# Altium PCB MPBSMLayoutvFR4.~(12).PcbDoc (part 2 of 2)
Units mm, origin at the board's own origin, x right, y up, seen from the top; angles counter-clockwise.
Board outline 131.7 x 110.39 mm, 4 copper layers (Top Layer, Power, GroundPlane, Bottom Layer), stack 2.286 mm thick; 156 components, 77 nets, 429 pads, 117 vias.
Unrouted connection lines stored in the file: 25.
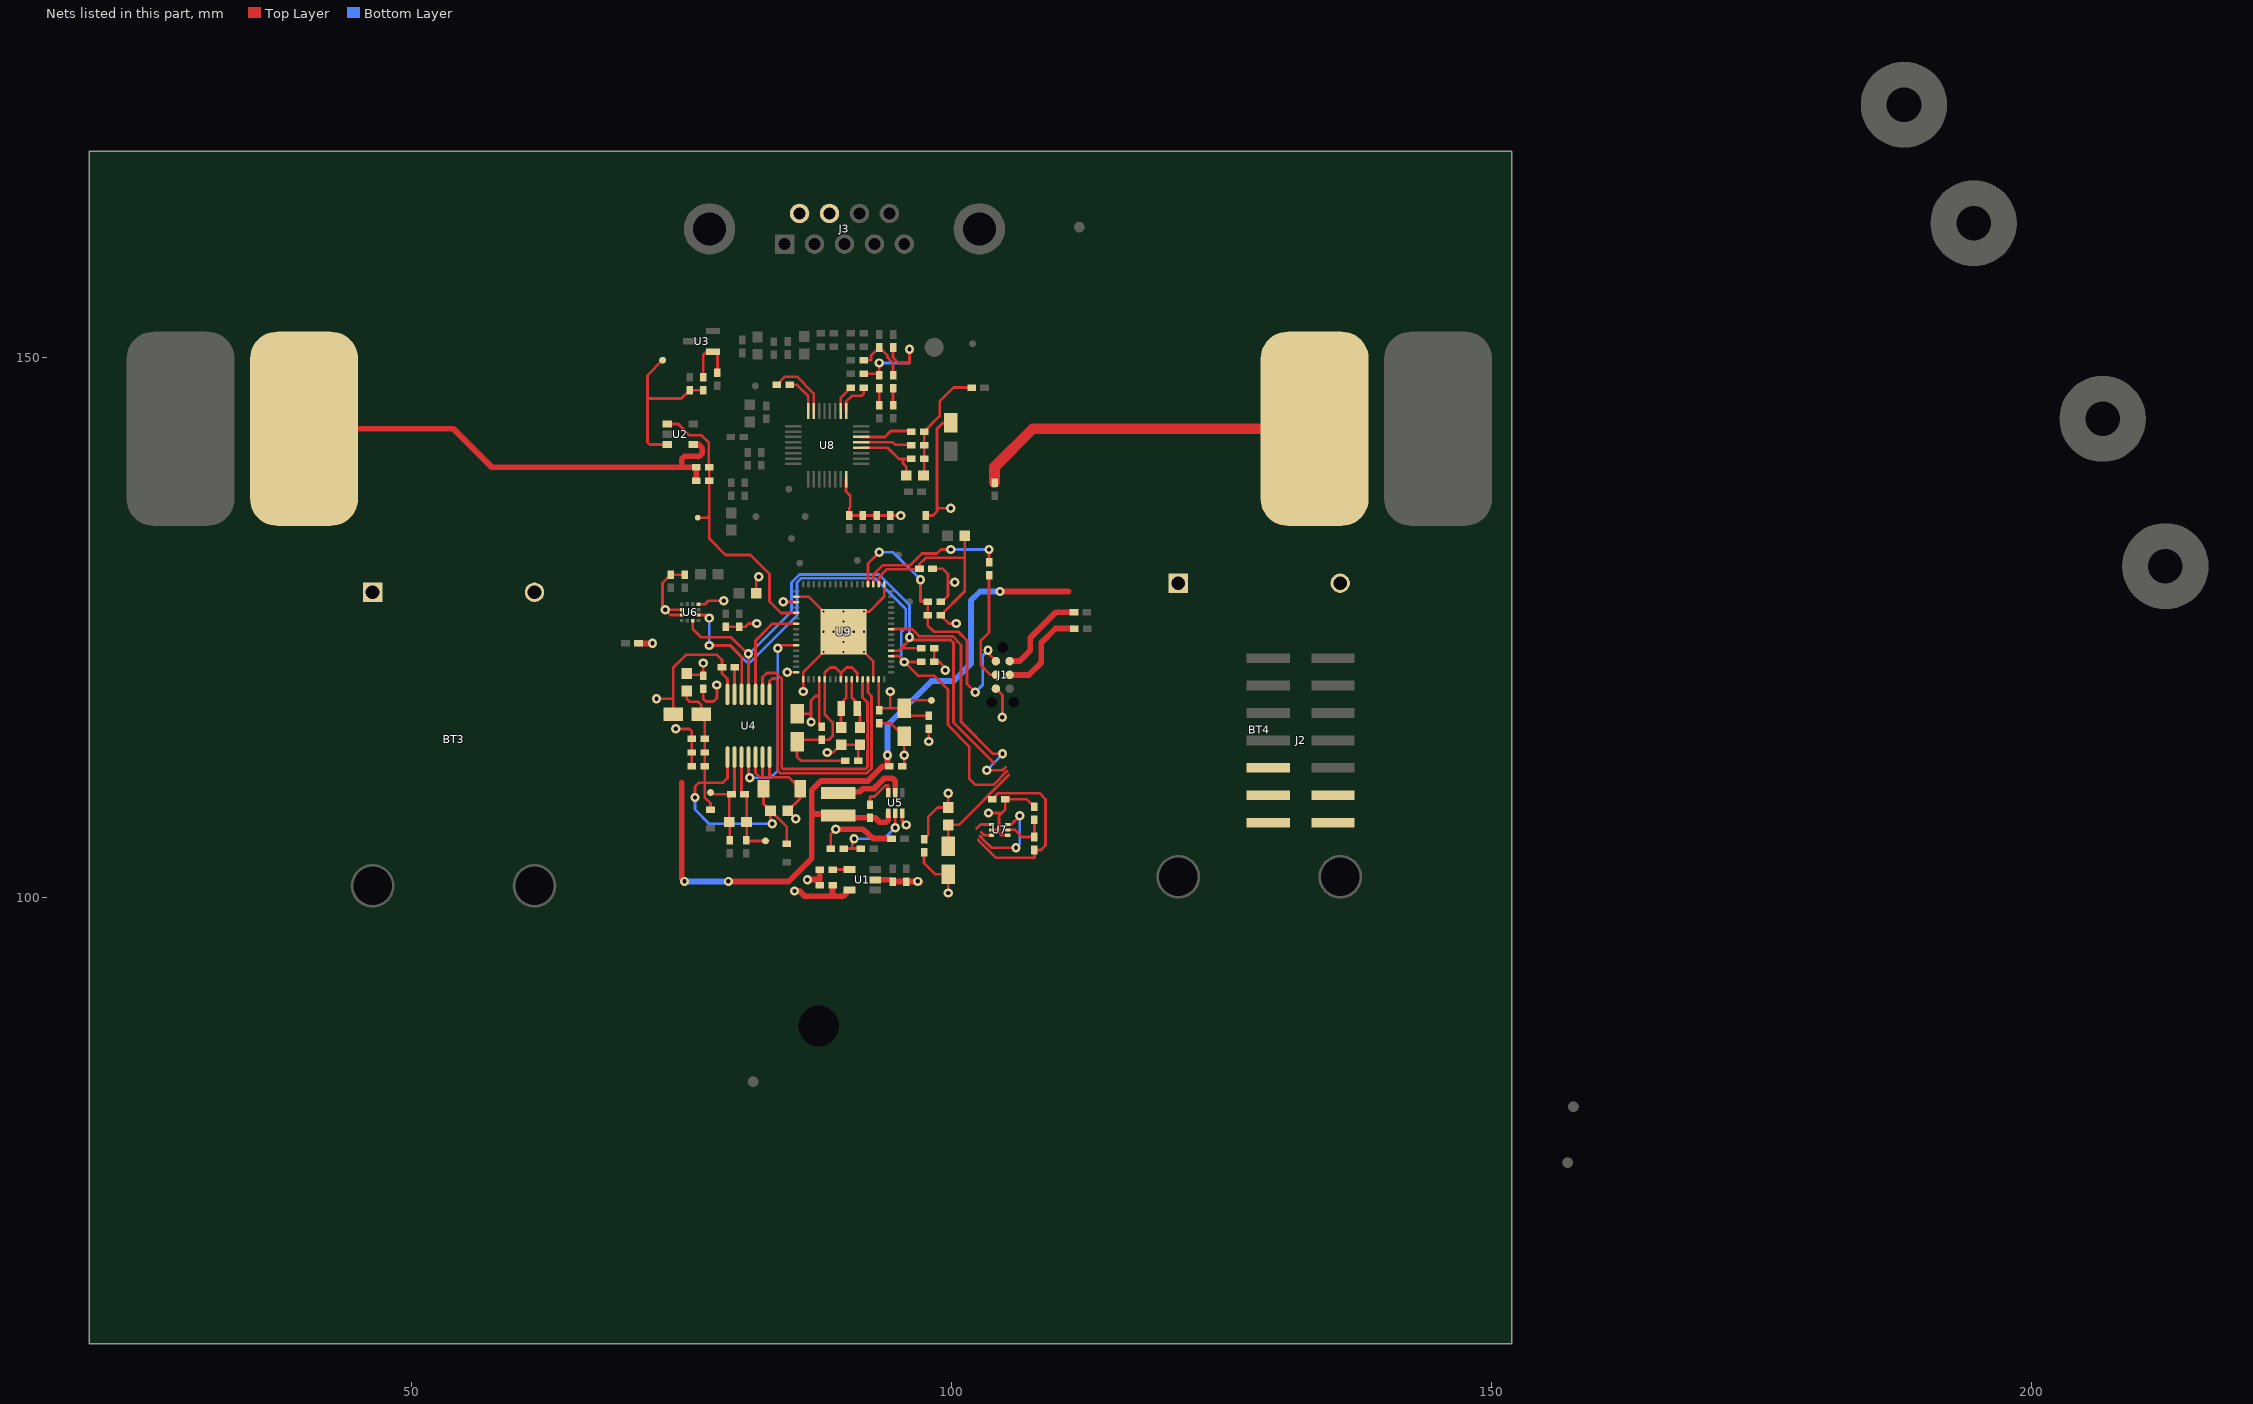
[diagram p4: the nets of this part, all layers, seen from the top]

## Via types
v1: diameter 0.864, hole 0.406, Top Layer to Bottom Layer, 104 vias
v2: diameter 0.5, hole 0.2, Top Layer to Bottom Layer, 13 vias

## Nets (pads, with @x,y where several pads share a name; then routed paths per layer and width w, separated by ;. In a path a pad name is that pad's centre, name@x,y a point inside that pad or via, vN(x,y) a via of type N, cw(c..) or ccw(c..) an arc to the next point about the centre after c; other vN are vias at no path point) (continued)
BOOST_INPUT: BT3.1 BT4.1 C34.1 L7.1 R16.1 U5.1 | length 73.3
  Top Layer w0.254: L7.1@89.561,107.681 L7.1@89.57,107.672 ; v1(94.107,113.132) v1@94.269,112.97
  Top Layer w0.5: 75.057,110.592 75.057,101.702 v1(75.311,101.448)
  Top Layer w0.54: v1(79.375,101.448) 84.963,101.448 87.097,103.581 87.097,109.906 87.935,110.744 92.278,110.744 93.65,112.116 C34.1@94.269,112.116 ; 87.097,107.696 L7.1@89.561,107.681 ; L7.1@89.781,107.35 R16.1@92.481,107.35 92.967,107.35 93.383,106.934 93.955,106.934 94.168,107.148 U5.1@94.168,107.762 ; C34.1@94.107,112.278 v1(94.107,113.132) ; v1(104.521,128.287) 110.87,128.287
  Bottom Layer w0.54: v1(75.311,101.448) v1(79.375,101.448) ; v1(94.107,113.132) 94.107,115.926 98.171,119.99 100.203,119.99 101.82,121.606 101.82,127.448 102.659,128.287 v1(104.521,128.287)
DVCC: 1.1 C1.1 C5.1 C6.1 C10.1 C14.1 C18.1 L1.1 L2.1 L3.1 L5.1 R1.1 R6.2 R31.1 R32.1 U1.5 U9.18 U9.35 U9.48 U9.63 | length 53
  Top Layer w0.254: L1.1@75.311,120.59 76.889,120.59 C10.1@76.913,120.613 ; C10.1@77.038,120.488 v1(77.038,121.666) ; L3.1@81.953,128.118 81.953,129.426 v1(82.169,129.642) ; v1@84.499,127.312 U9.35@85.643,127.312 ; v1(84.825,120.812) U9.48@85.643,120.812 ; U9.63@93.294,120.162 93.294,117.339 C6.1@93.345,117.288 ; U9.18@93.294,128.962 93.34,129.008 93.34,129.637 94.059,130.356 97.015,130.356 C18.1@97.063,130.404 97.063,130.82 97.663,131.42 101.219,131.42 ; C6.1@93.537,117.48 C1.1@95.631,117.48 ; 94.364,117.483 v1(94.364,119.027) ; C14.1@97.487,105.35 97.866,105.728 97.866,107.414 98.737,108.286 L2.1@99.728,108.286 v1(99.728,109.621) ; R1.1@97.917,116.78 96.331,116.78 C1.1@95.631,117.48 ; 1.1@98.171,118.212 96.363,118.212 C1.1@95.631,117.48 ; R32.1@98.425,123.038 R31.1@98.425,121.768 98.933,121.768 99.441,121.26 v1(99.441,121.006) ; v1(100.457,125.324) 99.787,125.324 R6.2@99.025,126.086 101.257,128.318 L5.1@101.257,133.452
  Top Layer w0.54: v1(85.496,100.559) v1@85.903,100.559 ; 85.928,100.584 86.436,100.076 89.022,100.076 ; C5.1@89.022,101.092 89.022,100.076 ; U1.5@90.57,100.65 89.996,100.076 89.022,100.076
  other v1: 84.455,127.356
EL_GSR1: C26.2 J3.7 R10.1 TP2.1 U2.4 | length 43.3
  Top Layer w0.254: U2.4@76.119,141.9 76.631,141.9
  Top Layer w0.54: TP2.1@40.081,143.358 53.899,143.358 57.455,139.802 R10.1@76.397,139.802 C26.2@76.397,138.532 ; 75.057,139.852 75.057,140.564 75.311,140.818 76.697,140.818 76.951,141.072 76.951,141.58 76.631,141.9
EL_GSR2: J3.6 R9.2 TP1.1 | length 32.6
  Top Layer w1: R9.2@104.013,138.37 104.013,139.827 107.544,143.358 TP1.1@133.655,143.358
GND: BT3.2 BT4.2 C1.2 C3.2 C4.2 C5.2 C6.2 C8.2 C9.2 C10.2 C11.2 C12.2 C13.2 C14.2 C15.2 C16.2 C17.2 C18.2 C19.2 C20.2 C21.2 C25.2 C27.2 C28.2 C29.1 C32.2 C33.2 C34.2 C35.2 C36.2 C37.2 C38.2 C41.2 C42.2 C58.2 C59.2 J1.6 J2.6 R2.1 R3.1 R17.1 U1.2 U4.5 U4.6 U4.7 U4.14 U5.3 U6.4 U6.8 U6.9 U7.2 U7.4 U8.24 U9.17 U9.34 U9.49 U9.62 U9.65 | length 145.9
  Top Layer w0.254: v1(72.72,118.364) 74.265,118.364 ; C9.2@74.265,116.942 74.265,118.364 ; v1(74.498,115.57) 75.768,115.57 75.981,115.357 C27.2@75.981,114.656 C11.2@75.981,113.386 C28.2@75.981,112.116 ; U6.9@75.044,126.111 74.016,126.111 v1(73.533,126.594) ; U6.8@75.044,126.611 73.55,126.611 v1(73.533,126.594) ; C37.2@75.311,129.847 C16.2@74.041,129.847 73.279,129.085 73.279,126.848 v1(73.533,126.594) ; U6.4@76.594,127.111 77.198,127.111 77.52,127.433 v1(78.94,127.433) ; C10.2@77.038,119.288 77.038,118.364 77.292,118.11 77.997,118.11 78.308,118.422 v1(78.308,119.634) ; C36.2@79.121,125.024 C17.2@80.391,125.024 80.947,125.024 81.247,125.324 v1(81.991,125.324) ; U4.14@79.286,118.764 79.286,120.193 78.775,120.704 C29.1@78.775,121.26 78.775,121.961 78.308,122.428 75.433,122.428 74.265,121.26 74.265,118.364 ; U4.5@81.886,112.964 81.886,111.484 82.271,111.1 83.185,111.1 ; 82.536,111.137 U4.6@82.536,112.964 ; U4.7@83.186,112.964 83.185,111.1 ; v1(85.62,107.266) 85.595,107.266 C33.2@84.87,107.991 86.024,109.145 C32.2@86.024,110.023 84.947,111.1 83.185,111.1 ; U9.34@85.643,127.812 86.793,127.812 v2(88.168,126.437) v2(90.043,124.562) ; v1(86.292,119.033) U9.49@86.292,120.162 86.292,120.811 v2(88.168,122.687) v2(90.043,124.562) ; v1(86.69,101.6) v1@86.703,101.613 ; v1(88.519,113.386) 89.065,113.386 89.789,114.11 C58.2@91.567,114.11 ; R17.1@88.843,104.496 88.843,105.812 v1(89.305,106.274) ; U8.24@90.269,138.704 90.269,137.544 90.651,137.162 90.651,136.099 90.551,135.999 C42.2@90.551,135.322 C41.2@91.821,135.322 C19.2@93.091,135.322 C20.2@94.361,135.322 v1@95.266,135.322 ; R2.1@91.405,112.624 C58.2@91.405,113.948 ; U9.62@92.794,120.162 92.794,121.811 v2(91.918,122.687) v2(90.043,124.562) ; C6.2@93.345,115.888 C6.2@93.345,116.088 94.423,116.088 C1.2@95.631,114.88 95.65,114.861 v1(95.65,113.132) 95.65,112.296 C34.2@95.469,112.116 C34.2@95.631,111.954 ; U9.17@93.794,128.962 93.794,127.805 92.426,126.437 v2(91.918,126.437) v2(90.043,124.562) ; C3.2@94.397,101.6 C3.2@94.569,101.428 ; v1(96.901,101.448) 96.901,101.194 v1@97.135,101.428 ; C14.2@97.487,104.15 97.487,103.147 98.513,102.122 C12.2@99.728,102.122 v1(99.728,100.374) ; C21.2@97.663,135.322 98.314,135.322 98.679,135.687 98.679,143.358 99.217,143.896 C15.2@99.949,143.896 C15.2@99.949,144.374 ; C18.2@98.263,130.404 99.187,130.404 99.695,129.896 99.695,129.134 ; 98.679,135.992 v1(99.949,135.992) ; C25.2@99.025,127.356 99.187,127.356 99.695,127.864 99.695,129.134 ; v1(100.33,129.134) 99.695,129.134 ; v1(103.449,107.783) 104.694,107.783 ; U7.2@103.728,106.221 104.398,106.221 ; J1.6@104.14,119.304 104.75,118.694 104.75,116.688 v1(104.724,116.662) ; U7.4@105.228,105.721 104.673,105.721 104.423,105.971 104.423,107.512 104.694,107.783 ; C38.2@107.706,108.352 106.99,109.068 C13.2@105.004,109.068 105.004,108.093 104.694,107.783
  Top Layer w0.354: U5.3@95.468,107.762 95.468,107.046 v1(95.834,106.68)
  Top Layer w0.54: R3.1@71.044,123.489 v1(72.346,123.489) ; v1@86.703,101.613 87.822,101.613 ; C5.2@87.822,101.092 87.822,101.613 ; C8.2@87.822,102.54 87.822,101.613 ; v1(89.305,106.274) 90.621,106.274 91.821,106.274 92.786,105.41 C35.2@94.522,105.41 ; U1.2@92.97,101.6 C3.2@94.397,101.6 ; C3.2@94.569,101.428 C4.2@95.839,101.428 v1@97.135,101.428
  other v1: 95.326,135.322
  other v2: 90.043,122.687 90.043,123.624 88.168,124.562 89.106,124.562 90.98,124.562 91.918,124.562 90.043,125.499 90.043,126.437
GSR_ANALOG_OUTPUT: 2.1 C26.1 R10.2 U2.1 U9.37 | length 26.9
  Top Layer w0.254: U2.1@73.719,143.8 74.725,143.8 75.777,142.748 76.895,142.748 77.555,142.088 77.555,140.14 77.597,140.098 R10.2@77.597,139.802 C26.1@77.597,138.532 77.597,135.23 ; 2.1@76.53,135.128 77.495,135.128 ; 77.495,135.23 77.597,135.23 ; U9.37@85.643,126.312 84.229,126.312 83.185,127.356 83.185,129.896 81.407,131.674 79.121,131.674 77.597,133.198 77.597,135.23
JTAG_TCK: J1.4 J2.4 R7.1 | length 10.4
  Top Layer w0.254: R7.1@103.505,129.804 103.505,124.511 102.743,123.749 102.743,121.463 103.632,120.574 J1.4@104.14,120.574
JTAG_TDO/TDI: C25.1 J1.2 J2.2 R6.1 U9.20 | length 28.1
  Top Layer w0.254: U9.20@92.294,128.962 92.294,130.876 v1(93.345,131.928) ; v1(97.155,129.388) 97.155,127.356 C25.1@97.825,127.356 R6.1@97.825,126.086 97.825,125.162 98.425,124.562 100.651,124.562 101.473,123.74 101.473,119.736 v1(102.235,118.974) ; v1(103.403,122.843) 103.403,122.58 J1.2@104.14,121.844
  Bottom Layer w0.254: v1(93.345,131.928) 94.615,131.928 v1(97.155,129.388) ; v1(102.235,118.974) 102.921,119.659 102.921,122.36 v1(103.403,122.843)
JTAG_TEST/SBWTCK: R7.2 U9.19 | length 13.7
  Top Layer w0.254: U9.19@92.794,128.962 92.794,129.852 93.651,130.71 96.191,130.71 97.282,131.801 98.677,131.801 99.058,132.182 v1(99.949,132.182) ; R7.2@103.505,131.004 v1(103.505,132.182)
  Bottom Layer w0.254: v1(99.949,132.182) v1(103.505,132.182)
JTAG_VCC_TARGET_IN: J1.3 J2.3 R5.1 | length 8.8
  Top Layer w0.54: J1.3@105.41,120.574 107.213,120.574 108.331,121.691 108.331,122.707 108.331,123.546 109.646,124.861 R5.1@111.382,124.861
JTAG_VCC_TOOL_OUT: J1.1 J2.1 R4.1 | length 8.5
  Top Layer w0.54: J1.1@105.41,121.844 106.324,121.844 107.315,122.834 107.315,124.003 109.677,126.365 R4.1@111.363,126.365
MSP_AVCC: C2.1 C7.1 R1.2 U9.52 | length 9.3
  Top Layer w0.254: C2.1@86.044,116.972 87.025,116.972 ; v1(87.025,116.21) 87.025,116.972 ; C7.1@87.792,115.982 87.792,118.618 ; U9.52@87.792,120.162 87.792,118.618 ; v1(97.917,114.402) R1.2@97.917,115.58 ; 87.025,116.972 87.025,118.191 87.452,118.618 87.792,118.618
MSP_AVSS: C2.2 C7.2 R2.2 U9.53 U9.56 U9.59 | length 20.5
  Top Layer w0.254: C2.2@85.725,114.372 85.725,112.979 86.081,112.624 R2.2@90.205,112.624 ; C2.2@85.917,114.564 C7.2@88.011,114.564 88.681,114.564 89.027,114.91 89.027,116.18 88.293,116.914 U9.53@88.293,120.162 88.293,120.779 88.773,121.26 89.281,121.26 89.785,120.756 ; U9.56@89.793,120.162 89.793,120.756 90.297,121.26 90.805,121.26 91.293,120.771 U9.59@91.293,120.162
MSP_LFXIN: C59.1 U9.57 Y1.1 | length 4.1
  Top Layer w0.254: C59.1@89.789,115.71 89.789,117.438 Y1.1@89.801,117.45 ; Y1.1@89.801,117.97 90.293,118.462 U9.57@90.293,120.162
MSP_LFXOUT: C58.1 U9.58 Y1.2 | length 4.3
  Top Layer w0.254: U9.58@90.793,120.162 90.793,118.477 Y1.2@91.301,117.97 ; Y1.2@91.301,117.45 91.567,117.184 C58.1@91.567,115.71
MSP_P1.0_INT: U4.10 U9.39 | length 9.4
  Top Layer w0.254: U4.10@81.886,118.764 81.886,123.749 ; 81.902,123.749 83.464,125.312 U9.39@85.643,125.312
MSP_P2.7_INT: U7.3 U9.9 | length 24.2
  Top Layer w0.254: U9.9@94.443,124.812 96.367,124.812 97.025,124.154 100.103,124.154 100.911,123.346 100.911,116.234 103.886,113.259 v1(104.75,113.259) ; 102.79,105.989 103.058,105.721 U7.3@103.728,105.721 ; v1@103.31,111.743 104.771,111.743 105.039,112.011
  Bottom Layer w0.254: v1(103.302,111.735) v1(104.75,113.259)
MSP_P4.0_INT: U4.9 U9.60 | length 28.4
  Top Layer w0.254: U4.9@82.536,118.764 82.536,120.356 82.931,120.752 83.798,120.752 84.301,120.248 84.301,112.016 84.455,111.862 92.075,111.862 92.26,112.046 92.26,113.506 92.269,113.516 92.269,114.704 92.26,114.713 92.26,115.106 92.269,115.116 92.269,116.304 92.26,116.313 92.26,118.027 91.793,118.493 U9.60@91.793,120.162
MSP_P4.1_INT: U4.8 U9.61 | length 27.8
  Top Layer w0.254: U4.8@83.186,118.764 83.186,119.99 83.439,120.244 83.693,120.244 83.947,119.99 83.947,111.718 84.211,111.454 92.175,111.454 ; 92.175,111.461 92.614,111.9 92.614,113.36 92.623,113.369 92.623,118.612 92.294,118.942 U9.61@92.294,120.162
MSP_P9.3_OUT: U4.4 U9.43 | length 18
  Top Layer w0.254: U4.4@81.236,112.964 81.236,111.169 v1(81.356,111.049) ; v1(83.947,123.038) 84.221,123.312 U9.43@85.643,123.312
  Bottom Layer w0.254: v1(81.356,111.049) 83.278,111.049 83.947,111.718 v1(83.947,123.038)
MSP_UCB0SCL_TMP103_SCL_RF430CL330HCPW_SCL: R32.2 U4.11 U6.12 U7.1 U9.5 | length 56.8
  Top Layer w0.254: U6.12@76.069,125.586 76.069,124.82 76.835,124.054 79.629,124.054 v1@81.185,122.497 ; U4.11@81.236,118.764 v1@81.236,122.447 ; U9.5@94.443,122.812 95.151,122.812 95.377,123.038 ; v1(96.139,124.054) v1@96.139,123.8 ; R32.2@97.063,123.038 95.377,123.038 ; 102.34,106.343 102.718,106.721 U7.1@103.728,106.721 ; 103.993,112.365 103.81,112.547 100.203,116.18 100.203,123.546 99.949,123.8 v1@96.139,123.8 ; 95.377,123.038 v1@96.139,123.8
  Bottom Layer w0.254: v1(81.227,122.539) 81.236,122.531 81.236,122.447 85.217,126.428 85.217,129.134 85.949,129.866 93.315,129.866 96.139,127.042 v1(96.139,124.054)
MSP_UCB0SDA_TMP103_SDA_RF430CL330HCPW_SDA: R31.2 U4.12 U6.2 U7.6 U9.4 | length 70.6
  Top Layer w0.254: U6.2@76.594,126.111 77.318,126.111 v1(77.597,125.832) ; v1(77.597,123.292) 79.543,123.292 80.602,122.233 80.602,118.78 U4.12@80.586,118.764 ; U9.4@94.443,122.312 95.123,122.312 v1(95.667,121.768) ; R31.2@97.225,121.768 v1(95.667,121.768) ; 102.644,105.635 102.947,105.332 102.954,105.332 103.716,104.57 v1(106.002,104.57) ; 105.186,111.657 103.917,110.388 102.235,110.388 101.663,110.96 101.663,113.957 99.695,115.926 99.695,119.228 98.425,120.498 96.937,120.498 v1(95.667,121.768) ; U7.6@105.228,106.721 105.562,106.721 v1(106.358,107.516)
  Bottom Layer w0.254: v1(77.597,125.832) v1(77.597,123.292) 79.543,123.292 81.067,121.768 81.407,121.768 85.725,126.086 85.725,129.134 86.103,129.512 92.967,129.512 95.785,126.694 95.785,124.97 95.377,124.562 95.377,122.058 v1(95.667,121.768) ; v1(106.002,104.57) 106.358,104.925 v1(106.358,107.516)
Net3_1: 3.1 R11.1 R12.2 U2.3 | length 15.6
  Top Layer w0.254: 71.871,146.152 75.008,146.152 R12.2@75.774,146.917 R11.1@77.044,146.917 ; 3.1@73.279,149.708 71.871,148.3 71.871,142.088 72.059,141.9 U2.3@73.719,141.9
Net4_1: 4.1 C30.1 C31.1 R13.1 U4.2 | length 9.9
  Top Layer w0.254: 4.1@77.72,109.676 77.881,109.515 C31.1@79.66,109.515 ; R13.1@79.498,105.255 79.498,106.903 C30.1@79.46,106.941 79.46,109.315 C31.1@79.66,109.515 ; U4.2@79.936,112.964 79.936,109.791 C31.1@79.66,109.515
Net5_1: 5.1 C30.2 C31.2 R14.1 U4.3 | length 9.9
  Top Layer w0.254: U4.3@80.586,112.964 80.586,109.788 C31.2@80.86,109.515 81.06,109.315 C30.2@81.06,106.941 81.06,105.293 81.156,105.197 5.1@83.054,105.197
NetC8_1: C8.1 U1.4 | length 1.6
  Top Layer w0.254: C8.1@89.017,102.54 89.028,102.55 U1.4@90.57,102.55
NetC29_2: C29.2 U4.13 | length 2.5
  Top Layer w0.254: U4.13@79.936,118.764 79.936,121.22 C29.2@79.975,121.26
NetC38_1: C38.1 R18.1 U7.5 | length 4.3
  Top Layer w0.254: U7.5@105.228,106.221 105.901,106.221 106.564,105.558 R18.1@107.706,105.558 C38.1@107.706,107.152
NetC43_1: C43.1 R19.2 R20.2 R21.2 R22.1 | length 10.9
  Top Layer w0.254: C43.1@97.501,139.094 R20.2@97.501,140.564 R21.2@97.501,141.834 97.501,141.876 R19.2@97.501,143.104 98.933,144.536 98.933,145.898 99.653,146.618 100.203,147.168 R22.1@101.889,147.168
NetC43_2: C43.2 R20.1 U8.28 | length 6.7
  Top Layer w0.254: U8.28@91.669,141.603 94.121,141.603 95.161,140.564 95.529,140.564 ; C43.2@95.847,139.04 95.847,139.818 95.529,140.135 95.529,140.564 ; R20.1@96.301,140.564 95.529,140.564
NetC45_1: C45.1 U8.2 | length 2.6
  Top Layer w0.254: U8.2@89.769,145.003 89.769,146.224 C45.1@90.713,147.168
NetC45_2: C45.2 U8.1 | length 3.4
  Top Layer w0.254: U8.1@90.269,145.003 90.269,145.87 90.805,146.406 91.707,146.406 91.913,146.612 C45.2@91.913,147.168
NetC46_2: C46.2 C48.2 C49.2 | length 10.4
  Top Layer w0.254: C46.2@91.913,148.45 C49.2@93.216,148.45 ; C49.2@93.345,148.322 v1(93.345,149.454) ; C48.2@94.615,150.886 94.621,150.88 94.621,149.967 95.134,149.454 96.139,149.454 v1(96.139,150.724)
  Bottom Layer w0.254: v1(93.345,149.454) 96.139,149.454 v1(96.139,150.724)
NetC47_1: C47.1 U8.8 | length 3.5
  Top Layer w0.254: C47.1@85.055,147.422 85.725,147.422 86.769,146.378 U8.8@86.769,145.003
NetC47_2: C47.2 U8.7 | length 6
  Top Layer w0.254: C47.2@83.855,147.422 84.617,148.184 85.725,148.184 87.269,146.64 U8.7@87.269,145.003
NetC49_1: C49.1 R26.1 | length 1.6
  Top Layer w0.254: R26.1@93.345,145.528 C49.1@93.345,147.122
NetC52_2: C52.2 C53.2 C54.2 | length 5.3
  Top Layer w0.254: C54.2@91.913,149.708 92.583,149.708 92.583,150.124 C52.2@93.345,150.886 94.107,150.124 94.107,149.962 94.615,149.454 C53.2@94.615,148.322
NetC53_1: C53.1 R27.1 | length 1.6
  Top Layer w0.254: R27.1@94.615,145.528 C53.1@94.615,147.122
NetL7_2: L7.2 U5.5 | length 5.5
  Top Layer w0.254: 92.888,110.033 92.888,110.084
  Top Layer w0.54: L7.2@91.008,109.752 91.54,109.752 91.821,110.033 92.888,110.033 ; 92.888,110.084 93.468,110.664 93.802,110.998 94.564,110.998 94.818,110.744 U5.5@94.818,109.662
NetR8_1: R8.1 R11.2 U3.1 | length 5.5
  Top Layer w0.254: R11.2@77.044,148.117 77.044,150.17 77.409,150.536 78.359,150.536 R8.1@78.359,148.53
NetR15_1: R15.1 R17.2 U5.2 | length 8.1
  Top Layer w0.254: R17.2@90.043,104.496 90.84,104.496 ; v1(91.008,105.41) 90.84,105.242 90.84,104.496 ; R15.1@91.637,104.496 90.84,104.496 ; v1(94.818,106.426) U5.2@94.818,107.762
  Bottom Layer w0.254: v1(91.008,105.41) 93.802,105.41 v1(94.818,106.426)
NetR16_2: R16.2 U5.6 | length 3.5
  Top Layer w0.254: R16.2@92.481,108.55 92.481,109.271 92.532,109.322 92.913,109.322 93.918,110.327 94.158,110.327 94.158,109.672 U5.6@94.168,109.662
NetR19_1: R19.1 U8.30 | length 4.9
  Top Layer w0.254: U8.30@91.669,142.603 93.861,142.603 94.403,143.146 R19.1@96.301,143.146
NetR21_1: R21.1 U8.29 | length 4.7
  Top Layer w0.254: U8.29@91.669,142.103 94.599,142.103 94.827,141.876 R21.1@96.301,141.876
RF430_DVCC: C9.1 C11.1 C27.1 C28.1 C32.1 C33.1 D1.1 D2.1 L1.2 U4.1 | length 34
  Top Layer w0.254: 75.514,118.512 75.514,118.338 75.761,118.092 76.549,118.092 76.865,117.775 C9.1@76.865,116.942 C9.1@77.089,117.166 ; v1(76.276,109.22) 76.276,110.236 76.632,110.592 77.175,110.592 ; C28.1@77.181,112.116 C11.1@77.181,113.386 C27.1@77.181,114.656 C9.1@77.181,116.626 ; C28.1@77.273,112.024 77.175,111.926 77.175,110.592 ; D1.1@77.72,108.079 77.72,108.691 77.175,109.235 77.175,110.592 ; U4.1@79.286,112.964 79.286,111.01 78.867,110.592 77.175,110.592 ; C32.1@82.624,110.023 82.624,108.637 C33.1@83.27,107.991 ; v1(83.439,106.782) 83.27,106.951 C33.1@83.27,107.991 ; D2.1@84.785,104.989 84.785,106.475 C33.1@83.27,107.991
  Bottom Layer w0.254: v1(76.276,109.22) 76.276,108.102 77.597,106.782 v1(83.439,106.782)
TMP_DVCC: C12.1 C13.1 L2.2 R18.2 | length 27
  Top Layer w0.254: C12.1@99.728,104.722 L2.2@99.728,106.686 100.715,106.686 105.332,111.303 ; 102.497,105.281 104.148,103.63 107.706,103.63 R18.2@107.706,104.358 108.33,104.358 108.741,104.768 108.741,109.049 108.172,109.618 104.354,109.618 C13.1@103.804,109.068
pads on no net: BT3.3 BT3.4 BT4.3 BT4.4 FID1.1 FID2.1 FID3.1 H1.0 H2.0 H3.0 H4.0 H5.1 H6.1 H7.1 H8.1 H9.0 H10.0 H11.0 H12.0 J1.5 J1.MH1 J1.MH2 J1.MH3 J2.5 J2.7 J2.8 J2.9 J2.10 J2.11 J2.12 J2.13 J2.14 J3.3 J3.5 J3.8 J3.9 U3.3 U6.10 U8.17 U9.1 U9.2 U9.3 U9.6 U9.7 U9.8 U9.10 U9.11 U9.12 U9.13 U9.15 U9.21 U9.22 U9.23 U9.24 U9.36 U9.40 U9.41 U9.42 U9.44 U9.45 U9.46 U9.47 U9.50 U9.51 U9.54 U9.55 U9.64
copper on no net: | length 0.5
  Top Layer w0.254: 104.47,124.206 v1(104.47,124.714)

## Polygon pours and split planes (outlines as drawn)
DVCC on Power (split plane): 102.36,142.288 102.36,131.727 101.724,131.092 78.616,131.092 77.98,131.727 77.98,133.144 79.175,134.338 93.091,134.338 93.141,134.348 93.183,134.376 98.263,139.456 98.291,139.498 98.3,139.548 98.3,142.796 98.709,143.205 101.443,143.205
DVCC on Power (split plane): 87.536,117.065 87.882,116.61 87.882,112.624 87.891,112.574 87.919,112.532 87.961,112.504 88.011,112.494 95.977,112.494 96.027,112.504 96.069,112.532 96.993,113.456 97.021,113.498 97.03,113.548 97.03,115.796 98.794,115.796 98.794,115.57 98.794,113.937 98.333,113.477 97.056,112.2 96.593,111.737 86.752,111.737 86.108,112.41 86.108,116.653 86.523,117.089
DVCC on Power (split plane): 90.676,154.534 90.634,146.998 81.916,147.043 81.915,147.043 81.891,147.038 81.866,147.033 81.865,147.033 81.845,147.019 81.824,147.006 81.824,147.005 81.823,147.005 81.81,146.984 81.796,146.964 81.796,146.963 81.795,146.963 81.79,146.939 81.786,146.914 81.786,143.104 81.795,143.054 81.823,143.012 81.865,142.984 81.915,142.974 86.612,142.974 86.612,141.201 83.439,141.201 83.389,141.191 83.347,141.163 83.319,141.121 83.31,141.072 83.31,135.359 77.168,135.359 77.168,139.09 77.158,139.14 77.13,139.182 74.932,141.379 74.932,145.59 77.949,148.607 79.088,148.607 79.113,148.612 79.137,148.616 79.137,148.617 79.138,148.617 79.159,148.631 79.179,148.644 79.179,148.645 79.18,148.645 79.194,148.665 79.208,148.686 79.208,148.687 79.213,148.711 79.218,148.736 79.25,154.658 90.676,154.658
DVCC on Power (split plane): 151.407,158.471 151.407,59.159 20.729,59.159 20.729,168.527 151.407,168.527
ADS_AVSS on GroundPlane (split plane): 151.407,158.471 151.407,128.806 102.11,128.806 102.11,137.008 102.101,137.057 102.073,137.099 102.031,137.127 101.981,137.137 98.933,137.137 98.883,137.127 98.841,137.099 98.813,137.057 98.804,137.008 98.804,135.765 96.472,135.765 96.472,136.398 96.462,136.448 96.434,136.49 96.392,136.518 96.342,136.527 89.403,136.527 89.388,136.524 89.373,136.524 89.363,136.52 89.353,136.518 89.341,136.509 89.327,136.503 77.657,127.993 20.729,128.018 20.729,168.527 151.407,168.527
GND on GroundPlane (split plane): 101.852,128.676 101.861,128.627 101.889,128.585 101.931,128.557 101.981,128.547 151.407,128.547 151.407,59.159 20.729,59.159 20.729,127.759 77.699,127.734 77.748,127.744 77.79,127.772 77.793,127.776 77.809,127.784 89.445,136.269 96.213,136.269 96.213,135.636 96.223,135.586 96.251,135.544 96.293,135.516 96.342,135.507 98.933,135.507 98.983,135.516 99.025,135.544 99.053,135.586 99.062,135.636 99.062,136.878 101.852,136.878

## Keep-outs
Keep-Out Layer:
  text ".Layer_Name" at 157.226,108.306 h1.52

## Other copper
Top Layer:
  text ".Layer_Name" at 157.226,156.566 h1.52
Bottom Layer:
  text ".Layer_Name" at 157.226,154.026 h1.52
  text "SVN:" at 49.67,114.91 h1.52 r90
  text ".VersionControl_RevNumber" at 49.67,107.823 h1.52 r90
  text "UL94V-0" at 55.702,69.774 h1.52 r90
Power (plane layer: these items are gaps in the copper):
  rectangle: 74.803,69.952 100.203,99.67
  lines w0.254: 98.923,115.57 98.923,115.926 ; 98.923,115.926 98.519,115.926 96.901,115.926 96.901,113.548 95.977,112.624 88.231,112.624 88.011,112.624 88.011,116.654 87.601,117.193 86.469,117.219 85.979,116.705 85.979,112.358 86.697,111.608 92.165,111.608 96.647,111.608 97.148,112.108 98.425,113.386 98.923,113.884 98.923,115.926 ; 74.803,141.326 77.038,139.09 77.038,135.23 81.211,135.23 83.439,135.23 83.439,141.072 86.741,141.072 86.741,143.104 81.915,143.104 81.915,146.914 90.763,146.868 90.805,154.534 90.805,154.788 79.121,154.788 79.088,148.736 77.896,148.736 74.803,145.644 74.803,141.326 ; 77.851,131.674 77.851,133.198 79.121,134.468 93.091,134.468 98.171,139.548 98.171,142.85 98.656,143.334 101.496,143.334 102.489,142.342 102.489,131.674 101.778,130.962 78.562,130.962 77.851,131.674
GroundPlane (plane layer: these items are gaps in the copper):
  rectangle: 74.803,69.952 100.203,99.67
  lines w0.254: 20.066,127.889 77.699,127.864 ; 77.733,127.888 89.403,136.398 96.342,136.398 96.342,135.636 98.933,135.636 98.933,137.008 101.981,137.008 101.981,128.676 151.74,128.676

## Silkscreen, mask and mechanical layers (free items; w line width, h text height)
Top Overlay:
  region: 96.342,77.724 96.342,85.344 93.802,85.344 93.802,77.724
  lines w1: 73.889,70.891 101.016,70.891 101.016,98.222 73.889,98.222 73.889,70.891
  lines w2: 20.955,133.325 44.755,133.325 150.266,133.325 ; 48.946,60.96 48.946,132.918 48.946,167.716 ; 125.654,61.646 125.654,167.157
  text "GSR" at 130.073,153.289 h4
  text "ECG" at 141.453,153.238 h4
  text "ECG" at 24.714,152.806 h4
  text "GSR" at 37.363,152.756 h4
  text "GND" at 46.609,131.318 h1.02
  text "VCC" at 60.122,129.845 h1.02
  text ".Layer_Name" at 157.226,128.626 h1.52
  text "JTAG" at 106.756,126.009 h1.02
  text "BAT" at 110.566,122.987 h1.02
  text "VCC" at 62.001,121.361 h1.02
  text "GND" at 46.863,121.158 h1.02
  text "FOR DEMO PURPOSES ONLY" at 76.505,94.259 h1.02
  text "MPBSM" at 80.086,91.44 h1.02
  text "REV A" at 80.086,89.916 h1.02
  text "TI" at 92.177,87.884 h1.52
  text "©" at 94.818,87.63 h2.67
  text ".CopyrightYear" at 85.166,77.724 h1.52
  text "MADE IN U.S." at 78.816,75.438 h1.52
  text "NFC Antenna" at 80.569,68.504 h2
  text "-" at 50.927,67.666 h1.52 r90
  text "Place phone here" at 52.934,62.84 h10
Bottom Overlay:
  text ".Layer_Name" at 157.226,126.086 h1.52
Top Paste:
  text ".Layer_Name" at 157.226,123.546 h1.52
Bottom Paste:
  text ".Layer_Name" at 157.226,121.006 h1.52
Top Solder:
  text ".Layer_Name" at 157.226,118.466 h1.52
  text ".Layer_Name" at 157.226,115.926 h1.52
Bottom Solder:
  text ".Layer_Name" at 157.226,113.386 h1.52
Drill Guide:
  text ".Layer_Name" at 157.226,110.846 h1.52
M1 Board Outline:
  lines w0.254: 75.311,58.257 101.6,58.257
  text ".Layer_Name" at 157.226,151.486 h1.52
M2 Board Dimensions:
  rectangle: 17.577,32.982 20.752,36.157
  rectangle: 20.752,29.807 30.277,32.982
  lines w0.178: 17.577,32.982 42.977,32.982 ; 20.752,29.807 20.752,36.157 ; 23.927,29.807 23.927,36.157 ; 30.277,29.807 30.277,36.157 ; 36.627,29.807 36.627,36.157 ; 17.577,29.807 42.977,29.807 42.977,36.157 17.577,36.157 17.577,29.807
  text ".Layer_Name" at 18.034,37.338 h1.52
M3 3D STEP Top:
  text ".Layer_Name" at 157.226,148.946 h1.52
M4 3D STEP Bottom:
  text ".Layer_Name" at 157.226,146.406 h1.52
M5 Assembly Top:
  lines w0.254: 10.16,16.607 177.8,16.607 ; 10.16,21.772 177.851,21.772 ; 10.16,26.937 10.16,11.443 111.887,11.443 177.851,11.443 177.851,26.937 10.173,26.937 10.173,11.443 50.19,11.443 ; 72.771,11.443 72.771,26.937 ; 104.953,21.772 104.953,26.937 ; 126.289,21.772 126.289,26.937 ; 142.088,11.278 142.088,16.43
  text "COMPONENTS MARKED 'DNP' SHOULD NOT BE POPULATED." at 46.876,32.144 h1.52
  text "ASSEMBLY VARIANT:" at 46.863,29.21 h1.52
  text ".VariantName" at 73.177,29.21 h1.52
  text "PCB VIEWED FROM TOP SIDE" at 11.773,23.58 h1.52
  text "BOARD #:" at 74.676,23.58 h1.52
  text ".PRJ_Number" at 88.532,23.58 h1.52
  text "REV:" at 109.982,23.58 h1.52
  text ".PCB_Rev" at 117.386,23.58 h1.52
  text "SVN REV:" at 131.267,23.58 h1.52
  text ".VersionControl_RevNumber" at 144.12,23.58 h1.52
  text "IGNORE ->" at 11.773,18.428 h1.52
  text "PLOT NAME =" at 11.773,13.199 h1.52
  text ".plot_File_Name" at 32.233,13.199 h1.52
  text "GENERATED    :" at 74.727,13.199 h1.52
  text ".Print_Date" at 96.812,13.199 h1.52
  text ".Print_Time" at 115.329,13.199 h1.52
  text "TEXAS INSTRUMENTS" at 147.447,13.199 h1.52
M6 Assembly Bottom:
  lines w0.254: 10.147,21.759 177.838,21.759 ; 10.198,16.595 177.838,16.595 ; 45.91,11.265 45.91,16.417 ; 61.709,21.759 61.709,26.924 ; 83.045,21.759 83.045,26.924 ; 115.227,11.43 115.227,26.924 ; 137.808,11.43 177.825,11.43 177.825,26.924 10.147,26.924 10.147,11.43 76.111,11.43 177.838,11.43 177.838,26.924
  text "COMPONENTS MARKED 'DNP' SHOULD NOT BE POPULATED." at 172.568,32.156 h1.52
  text ".VariantName" at 146.05,29.21 h1.52
  text "ASSEMBLY VARIANT:" at 172.441,29.21 h1.52
  text ".VersionControl_RevNumber" at 43.878,23.567 h1.52
  text "SVN REV:" at 56.731,23.567 h1.52
  text ".PCB_Rev" at 70.612,23.567 h1.52
  text "REV:" at 78.016,23.567 h1.52
  text ".PRJ_Number" at 99.466,23.567 h1.52
  text "BOARD #:" at 113.322,23.567 h1.52
  text "PCB VIEWED FROM BOTTOM SIDE" at 176.225,23.567 h1.52
  text "IGNORE ->" at 82.292,18.428 h1.52
  text "TEXAS INSTRUMENTS" at 40.551,13.187 h1.52
  text ".Print_Time" at 72.669,13.187 h1.52
  text ".Print_Date" at 91.186,13.187 h1.52
  text "GENERATED    :" at 113.271,13.187 h1.52
  text ".plot_File_Name" at 155.766,13.187 h1.52
  text "PLOT NAME =" at 176.225,13.187 h1.52
M9 Title Sheet:
  drawing of 57 lines, arcs and shapes, not listed
  text "1" at 36.369,243.091 h1.78
  text "2" at 99.758,243.091 h1.78
  text "3" at 162.988,243.091 h1.78
  text "4" at 226.657,243.091 h1.78
  text "5" at 290.131,243.091 h1.78
  text "6" at 353.758,243.091 h1.78
  text "A" at 6.998,214.058 h1.78
  text "A" at 382.918,214.058 h1.78
  text "B" at 6.998,153.606 h1.78
  text "B" at 382.918,153.606 h1.78
  text ".Layer_Name" at 157.226,143.866 h1.52
  text "C" at 6.998,93.281 h1.78
  text "C" at 382.918,93.281 h1.78
  text "PROJECT TITLE:" at 305.702,46.012 h1.14
  text ".PRJ_Title" at 306.972,42.626 h1.78
  text "DESIGNED FOR:" at 305.702,38.367 h1.14
  text ".PRJ_Customer" at 306.972,34.811 h1.78
  text "D" at 6.998,33.084 h1.78
  text "D" at 382.918,33.084 h1.78
  text "FILE NAME:" at 305.702,30.747 h1.14
  text ".PCB_File_Name_No_Path" at 306.972,27.699 h1.78
  text "Texas Instruments (TI) and/or its licensors do not warrant the accuracy or completeness of this specification" at 179.476,23.588 h1.14
  text "ENGINEER:" at 305.702,23.381 h1.14
  text "LAYOUT BY:" at 343.929,23.381 h1.14
  text "or any information contained therein. TI and/or its licensors do not warrant that this design will meet" at 178.334,20.726 h1.14
  text ".PRJ_Engineer" at 306.972,19.444 h1.78
  text ".PCB_Layout" at 345.211,19.444 h1.78
  text "the specifications, will be suitable for your application or fit for any particular purpose, or will operate in" at 178.334,17.865 h1.14
  text "ALTIUM DESIGNER VERSION:" at 343.929,15.507 h1.14
  text "an implementation. TI and/or its licensors do not warrant that the design is production worthy. You should" at 178.334,15.003 h1.14
  text "completely validate and test your design implementation to confirm the system functionality for your application." at 179.476,12.141 h1.14
  text ".print_Scale" at 306.972,12.12 h1.78
  text ".Application_BuildNumber" at 345.211,12.12 h1.78
  text "1" at 36.369,6.871 h1.78
  text "2" at 99.758,6.871 h1.78
  text "3" at 162.988,6.871 h1.78
  text "4" at 226.657,6.871 h1.78
  text "5" at 290.131,6.871 h1.78
  text "6" at 353.758,6.871 h1.78
M10 Fab Notes:
  drawing of 185 lines, arcs and shapes, not listed
  text "DESIGN INFORMATION" at 332.055,190.348 h1.52
  text "MIN. TRACK WIDTH:" at 315.683,185.776 h1.52
  text "8" at 343.527,185.776 h1.52
  text "MIL" at 347.458,185.776 h1.52
  text "MIN. CLEARANCE:" at 315.683,182.423 h1.52
  text "0.2" at 342.003,182.423 h1.52
  text "mm" at 347.458,182.423 h1.52
  text "MIN. VIA PAD SIZE:" at 315.683,179.07 h1.52
  text "24" at 342.766,179.07 h1.52
  text "MIL" at 347.458,179.07 h1.52
  text "0.05mm (2MIL)" at 333.336,175.471 h1.52
  text "MINIMUM ANNULAR RING" at 307.32,175.362 h1.52
  text "EXTERNAL" at 351.319,175.362 h1.52
  text "PER" at 312.4,172.364 h1.52
  text "IPC-D-275 CLASS 2 LEVEL C" at 317.988,172.364 h1.52
  text "MIL, HOLES" at 355.789,169.512 h1.52
  text "+/-" at 345.821,169.494 h1.52
  text "+/-" at 367.513,169.494 h1.52
  text "REGISTRATION TOLERANCES:" at 307.32,169.367 h1.52
  text "METAL" at 337.795,169.367 h1.52
  text "5" at 352.43,169.367 h1.52
  text "3" at 373.588,169.367 h1.52
  text "MIL" at 376.541,169.367 h1.52
  text "MATERIAL:" at 305.421,164.047 h1.52
  text "FR-4 High Tg" at 330.477,160.482 h1.52
  text "FR-408" at 316.115,160.265 h1.52
  text "X" at 326.579,160.265 h1.52
  text "OTHER" at 353.91,160.265 h1.52
  text "62 MIL (1.6mm) +/-10%" at 324.245,156.132 h1.52
  text "THICKNESS:" at 307.32,156.023 h1.52
  text "X" at 320.99,156.023 h1.52
  text "OTHER" at 356.882,156.023 h1.52
  text "TOLERANCE:" at 307.32,152.01 h1.52
  text "X" at 328.639,152.01 h1.52
  text "ANSI IPC-6012 TYPE 3 CLASS 2" at 333.387,152.01 h1.52
  text "OTHER +/-" at 333.387,148.047 h1.52
  text "BOW & TWIST:" at 307.32,144.06 h1.52
  text "X" at 328.639,144.06 h1.52
  text "ANSI IPC-6012 TYPE 3 CLASS 2" at 333.387,144.06 h1.52
  text ".Layer_Name" at 157.226,141.326 h1.52
  text "OTHER +/-" at 333.387,140.034 h1.52
  text "DRILLING:" at 305.421,136.516 h1.52
  text "REFERENCE:" at 307.32,133.544 h1.52
  text "X" at 323.785,133.544 h1.52
  text "AS SHOWN" at 328.535,133.544 h1.52
  text "X" at 346.671,133.544 h1.52
  text "NC_DRILL FILES" at 350.151,133.544 h1.52
  text "PTH MIN COPPER THICKNESS:" at 307.32,129.531 h1.52
  text "X" at 341.616,129.531 h1.52
  text "1MIL" at 345.096,129.531 h1.52
  text "OTHER" at 357.72,129.531 h1.52
  text "BOARD FINISH:" at 305.421,125.492 h1.52
  text "SILKSCREEN:" at 309.364,122.495 h1.52
  text "X" at 333.463,122.495 h1.52
  text "TOP" at 336.663,122.495 h1.52
  text "X" at 346.417,122.495 h1.52
  text "BOTTOM" at 349.643,122.495 h1.52
  text "SILKSCREEN COLOR:" at 310.634,118.26 h1.52
  text "X" at 333.436,118.253 h1.52
  text "WHITE" at 336.663,118.253 h1.52
  text "OTHER" at 349.643,118.253 h1.52
  text "SOLDER RESIST COLOR:" at 309.364,113.935 h1.52
  text "GREEN" at 327.011,109.892 h1.52
  text "BLUE" at 342.023,109.892 h1.52
  text "OTHER" at 355.688,109.892 h1.52
  text "X" at 323.785,109.644 h1.52
  text "IMMERSION GOLD (ENIG)" at 332.371,105.103 h1.52
  text "ENEPIG" at 366.344,105.02 h1.52
  text "SURFACE FINISH:" at 305.421,104.994 h1.52
  text "X" at 327.622,104.994 h1.52
  text "IMM. TIN/SILVER OR EQUIV" at 313.792,101.007 h1.52
  text "OTHER" at 350.151,101.007 h1.52
  text "ARRAY/PANEL:" at 305.421,96.46 h1.52
  text "CUT AND TRIM PER MECH LAYER 1" at 332.371,96.351 h1.52
  text "N.C. ROUTE" at 332.371,92.498 h1.52
  text "X" at 349.617,92.498 h1.52
  text "V. SCORE" at 354.367,92.498 h1.52
  text "CERTIFICATION:" at 305.421,89.018 h1.52
  text "MATERIALS AND WORKMANSHIP FOR ALL PCBS" at 323.836,89.018 h1.52
  text "TO MEET OR EXCEED THE REQUIREMENTS OF:" at 323.836,86.529 h1.52
  text "X" at 314.349,83.061 h1.52
  text "ANSI IPC-A-600F CLASS ->" at 317.88,83.061 h1.52
  text "X" at 359.512,83.061 h1.52
  text "2" at 362.533,83.061 h1.52
  text "1" at 354.532,83.023 h1.52
  text "3" at 371.525,83.023 h1.52
  text "X" at 314.402,79.01 h1.52
  text "UL 94V-0" at 317.88,79.01 h1.52
  text "X" at 335.026,79.01 h1.52
  text "RoHS" at 338.505,79.01 h1.52
  text "OTHER" at 354.873,79.01 h1.52
  text "PER ORDER" at 364.958,79.01 h1.52
  text "ADDITIONAL REQUIREMENTS:" at 305.193,75.302 h1.52
  text "MICROSECTION:" at 307.092,72.381 h1.52
  text "YES" at 330.098,72.381 h1.52
  text "REQUIRED" at 352.208,68.542 h1.52
  text "NONE" at 340.486,68.469 h1.52
  text "X" at 348.982,68.469 h1.52
  text "PER ORDER" at 367.245,68.469 h1.52
  text "BARE BOARD ELEC. TEST:" at 307.092,68.342 h1.52
  text "MANUFACTURER'S UL:" at 307.092,64.354 h1.52
  text "METAL" at 349.422,64.373 h1.52
  text "X" at 358.953,64.364 h1.52
  text "SILK" at 362.419,64.373 h1.52
  text "RAIL" at 336.702,64.245 h1.52
M11 Gerber Information:
  lines w0.254: 10.16,16.607 177.8,16.607 ; 10.16,21.772 177.851,21.772 ; 10.16,26.937 10.16,11.443 111.887,11.443 177.851,11.443 177.851,26.937 10.173,26.937 10.173,11.443 50.19,11.443 ; 72.771,11.443 72.771,26.937 ; 104.953,21.772 104.953,26.937 ; 126.289,21.772 126.289,26.937 ; 142.088,11.278 142.088,16.43
  text "ALL ARTWORK VIEWED FROM TOP SIDE" at 11.773,23.58 h1.52
  text "BOARD #:" at 74.676,23.58 h1.52
  text ".PRJ_Number" at 88.532,23.58 h1.52
  text "REV:" at 109.982,23.58 h1.52
  text ".PCB_Rev" at 117.386,23.58 h1.52
  text "SVN REV:" at 131.267,23.58 h1.52
  text ".VersionControl_RevNumber" at 144.12,23.58 h1.52
  text "LAYER NAME =" at 11.773,18.428 h1.52
  text "PLOT NAME =" at 11.773,13.199 h1.52
  text ".plot_File_Name" at 32.233,13.199 h1.52
  text "GENERATED    :" at 74.727,13.199 h1.52
  text ".Print_Date" at 96.812,13.199 h1.52
  text ".Print_Time" at 115.329,13.199 h1.52
  text "TEXAS INSTRUMENTS" at 147.447,13.199 h1.52
M12 Stackup:
  lines w0.152: 305.105,221.59 369.875,221.59 ; 305.105,224.241 369.875,224.241 ; 303.581,209.271 ccw(c304.444,209.271) 304.444,208.407 370.535,208.407 ccw(c370.535,209.271) 371.399,209.271 371.399,227.203 ccw(c370.535,227.203) 370.535,228.067 304.444,228.067 ccw(c304.444,227.203) 303.581,227.203 303.581,209.271
  text "The Stackup Legend below this is static." at 311.34,232.118 h1.52
  text "If you change the stackup, update the Legend." at 311.594,229.832 h1.52
  text "Layer Stack Up Detail for: Ref_Design.PcbDoc" at 305.105,225.072 h1.45
  text "Layer" at 305.105,223.251 h0.61
  text "Gerber" at 327.858,223.251 h0.61
  text "Copper" at 342.172,223.251 h0.61
  text "Dielectric" at 357.481,223.251 h0.61
  text "Name" at 305.105,222.032 h0.61
  text "Document" at 327.858,222.032 h0.61
  text "Thickness" at 342.172,222.032 h0.61
  text "Material" at 357.481,222.032 h0.61
  text "Top Solder Mask" at 305.105,219.67 h0.86
  text "(.GTS)" at 327.858,219.67 h0.86
  text "Solder Resist" at 357.481,219.67 h0.86
  text ".Layer_Name" at 284.988,218.186 h1.52
  text "Top Layer" at 305.105,217.213 h0.86
  text "(.GTL)" at 327.858,217.213 h0.86
  text "1.4mil" at 342.172,217.213 h0.86
  text "FR-4" at 357.481,215.984 h0.86
  text "Bottom Layer" at 305.105,214.755 h0.86
  text "(.GBL)" at 327.858,214.755 h0.86
  text "1.4mil" at 342.172,214.755 h0.86
  text "Bottom Solder Mask" at 305.105,212.298 h0.86
  text "(.GBS)" at 327.858,212.298 h0.86
  text "Solder Resist" at 357.481,212.298 h0.86
M13 Component Bodies Top:
  text ".Layer_Name" at 157.226,138.786 h1.52
M14 Component Bodies Bottom:
  text ".Layer_Name" at 157.226,136.246 h1.52
M15 Courtyards Top:
  text ".Layer_Name" at 157.226,133.706 h1.52
M16 Courtyards Bottom:
  text ".Layer_Name" at 157.226,131.166 h1.52
Drill Drawing:
  text ".Layer_Name" at 157.226,105.766 h1.52

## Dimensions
145.085,143.358 to 151.917,158.471 on M2 Board Dimensions
28.651,143.358 to 20.218,169.037 on M2 Board Dimensions
125.654,61.646 to 151.917,58.649 on M2 Board Dimensions
20.218,58.649 to 48.946,60.96 on M2 Board Dimensions
133.655,143.358 to 145.085,143.358 on M2 Board Dimensions
28.651,143.358 to 40.081,143.358 on M2 Board Dimensions
17.577,29.807 to 42.977,29.807 on M2 Board Dimensions
75.819,72.492 to 99.187,72.492 on M2 Board Dimensions
99.187,97.13 to 99.187,72.492 on M2 Board Dimensions
99.695,71.984 to 125.654,61.646 on M2 Board Dimensions
48.946,60.96 to 75.26,71.984 on M2 Board Dimensions
48.946,60.96 to 125.654,61.646 on M2 Board Dimensions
